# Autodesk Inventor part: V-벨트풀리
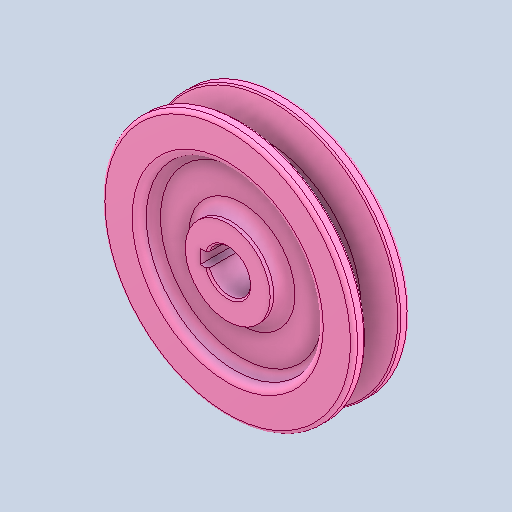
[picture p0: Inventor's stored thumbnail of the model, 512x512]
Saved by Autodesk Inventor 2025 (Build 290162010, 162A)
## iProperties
Created: 2024-08
Part Number: V-벨트풀리
Material: 강철, 연강
Document SubType Name: Modeling
Designer: 학생
Density: 7.86 g/cm^3
Appearance: 기본값
Author: jhkim
Sending System: Autodesk Inventor 2025
Preprocessor: ST-DEVELOPER v20
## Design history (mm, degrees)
feature "Solid1"
node "솔리드1"
